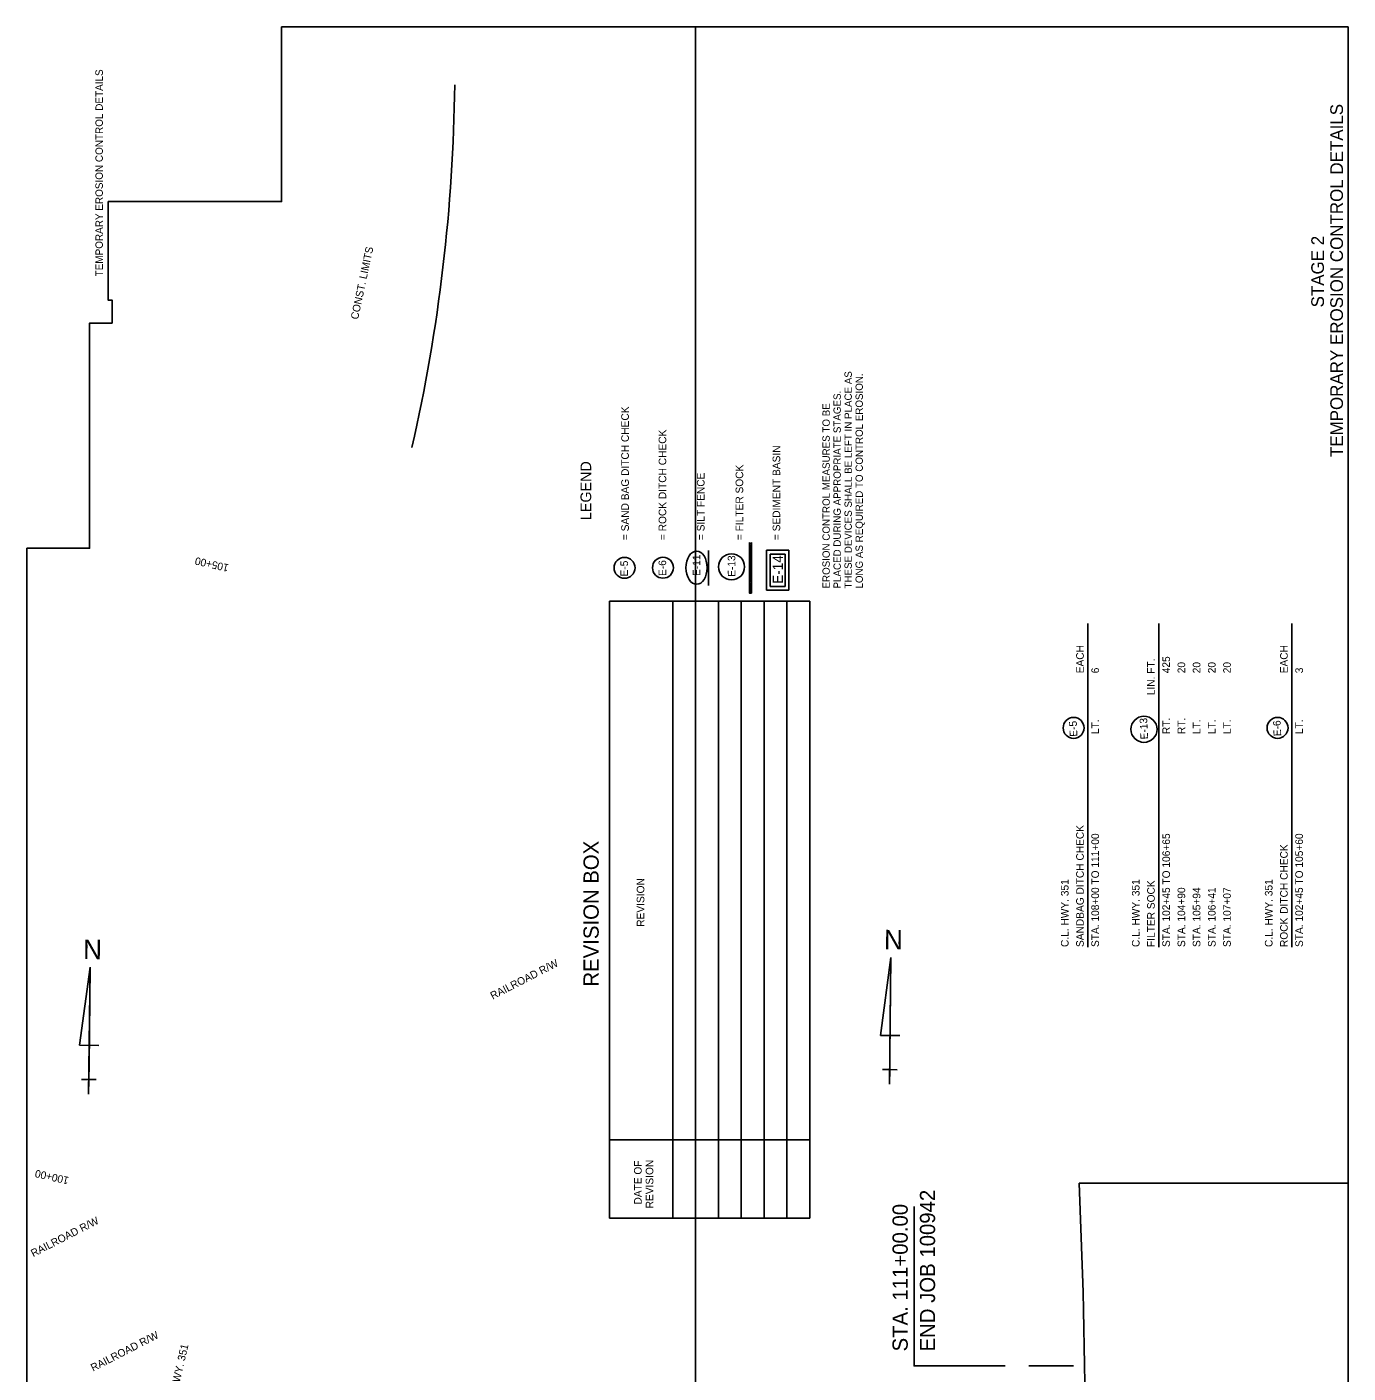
# Model space of a CAD drawing. Extents: x 1712161 to 1713203, y 549259 to 550855.
# Drawn here: x 1712161 to 1713203, y 549792 to 550855 of the extents above; entities that cross this region are included whole.
import ezdxf

# ---------------------------------------------------------------- set-up
doc = ezdxf.new("R2010")
doc.units = 0
for name, color, linetype in [('R_Contour Annot', 7, 'Continuous'), ('R_Contours', 7, 'Continuous'), ('R_Erosion', 7, 'Continuous'), ('R_Horz Alg', 7, 'Continuous'), ('R_Horz Alg Annot', 7, 'Continuous'), ('R_MOT', 7, 'Continuous'), ('R_Proposed Const Limits_Fill', 7, 'Continuous'), ('S_FENCE', 7, 'Continuous'), ('S_FIBER_OPTIC_CABLE', 7, 'Continuous')]:
    doc.layers.add(name, color=color, linetype=linetype)

msp = doc.modelspace()

# ---------------------------------------------------------------- linework, layer by layer
at = {"layer": 'R_Contour Annot'}
for points in [[(1712361.5, 550854.5), (1712688.2, 550854.5), (1712688.2, 549259.2), (1712160.6, 549259.2), (1712160.6, 550443.2), (1712210, 550443.2), (1712210, 550620.8), (1712227.8, 550620.8), (1712227.8, 550639), (1712224.6, 550639), (1712224.6, 550716.7)], [(1712361.5, 550854.5), (1712688.2, 550854.5), (1712688.2, 549259.2), (1712160.6, 549259.2), (1712160.6, 550443.2), (1712210, 550443.2), (1712210, 550620.8), (1712227.8, 550620.8), (1712227.8, 550639), (1712224.6, 550639), (1712224.6, 550716.7)], [(1712361.5, 550854.5), (1712688.2, 550854.5), (1712688.2, 549259.2), (1712160.6, 549259.2), (1712160.6, 550443.2), (1712210, 550443.2), (1712210, 550620.8), (1712227.8, 550620.8), (1712227.8, 550639), (1712224.6, 550639), (1712224.6, 550716.7)], [(1712361.5, 550854.5), (1712688.2, 550854.5), (1712688.2, 549259.2), (1712160.6, 549259.2), (1712160.6, 550443.2), (1712210, 550443.2), (1712210, 550620.8), (1712227.8, 550620.8), (1712227.8, 550639), (1712224.6, 550639), (1712224.6, 550716.7)], [(1712361.5, 550854.5), (1712688.2, 550854.5), (1712688.2, 549259.2), (1712160.6, 549259.2), (1712160.6, 550443.2), (1712210, 550443.2), (1712210, 550620.8), (1712227.8, 550620.8), (1712227.8, 550639), (1712224.6, 550639), (1712224.6, 550716.7)], [(1712361.5, 550854.5), (1712688.2, 550854.5), (1712688.2, 549259.2), (1712160.6, 549259.2), (1712160.6, 550443.2), (1712210, 550443.2), (1712210, 550620.8), (1712227.8, 550620.8), (1712227.8, 550639), (1712224.6, 550639), (1712224.6, 550716.7)], [(1712361.5, 550854.5), (1712688.2, 550854.5), (1712688.2, 549259.2), (1712160.6, 549259.2), (1712160.6, 550443.2), (1712210, 550443.2), (1712210, 550620.8), (1712227.8, 550620.8), (1712227.8, 550639), (1712224.6, 550639), (1712224.6, 550716.7)], [(1712361.5, 550854.5), (1712688.2, 550854.5), (1712688.2, 549259.2), (1712160.6, 549259.2), (1712160.6, 550443.2), (1712210, 550443.2), (1712210, 550620.8), (1712227.8, 550620.8), (1712227.8, 550639), (1712224.6, 550639), (1712224.6, 550716.7)], [(1712224.6, 550716.7), (1712361.5, 550716.7), (1712361.5, 550854.5)], [(1712224.6, 550716.7), (1712361.5, 550716.7), (1712361.5, 550854.5)], [(1712224.6, 550716.7), (1712361.5, 550716.7), (1712361.5, 550854.5)], [(1712224.6, 550716.7), (1712361.5, 550716.7), (1712361.5, 550854.5)], [(1712224.6, 550716.7), (1712361.5, 550716.7), (1712361.5, 550854.5)], [(1712224.6, 550716.7), (1712361.5, 550716.7), (1712361.5, 550854.5)], [(1712224.6, 550716.7), (1712361.5, 550716.7), (1712361.5, 550854.5)], [(1712224.6, 550716.7), (1712361.5, 550716.7), (1712361.5, 550854.5)]]:
    msp.add_lwpolyline(points, dxfattribs=at)
msp.add_lwpolyline([(1712688.2, 549259.2), (1712688.2, 550854.5), (1713202.9, 550854.5), (1713202.9, 549259.2)], close=True, dxfattribs=at)
msp.add_lwpolyline([(1712688.2, 549259.2), (1712688.2, 550854.5), (1713202.9, 550854.5), (1713202.9, 549259.2)], close=True, dxfattribs=at)
msp.add_lwpolyline([(1712688.2, 549259.2), (1712688.2, 550854.5), (1713202.9, 550854.5), (1713202.9, 549259.2)], close=True, dxfattribs=at)
msp.add_lwpolyline([(1712688.2, 549259.2), (1712688.2, 550854.5), (1713202.9, 550854.5), (1713202.9, 549259.2)], close=True, dxfattribs=at)
msp.add_lwpolyline([(1712688.2, 549259.2), (1712688.2, 550854.5), (1713202.9, 550854.5), (1713202.9, 549259.2)], close=True, dxfattribs=at)
msp.add_lwpolyline([(1712688.2, 549259.2), (1712688.2, 550854.5), (1713202.9, 550854.5), (1713202.9, 549259.2)], close=True, dxfattribs=at)
msp.add_lwpolyline([(1712688.2, 549259.2), (1712688.2, 550854.5), (1713202.9, 550854.5), (1713202.9, 549259.2)], close=True, dxfattribs=at)
msp.add_lwpolyline([(1712688.2, 549259.2), (1712688.2, 550854.5), (1713202.9, 550854.5), (1713202.9, 549259.2)], close=True, dxfattribs=at)
msp.add_lwpolyline([(1712688.2, 549259.2), (1712688.2, 550854.5), (1713202.9, 550854.5), (1713202.9, 549259.2)], close=True, dxfattribs=at)
at = {"layer": 'R_Contours'}
msp.add_arc((1711136.1, 550824.3), 1362.1, 347.2066, 359.3498, dxfattribs=at)
at = {"layer": 'R_Horz Alg'}
for p, q in [((1712842.3, 550120.2), (1712833.9, 550058.8)), ((1712841.2, 550020.2), (1712842.3, 550120.2)), ((1712842.3, 550120.2), (1712841.5, 550043.3)), ((1712210.4, 550112.5), (1712202.1, 550051)), ((1712209.3, 550012.5), (1712210.4, 550112.5)), ((1712210.4, 550112.5), (1712209.6, 550035.6)), ((1712202.1, 550051), (1712217.4, 550050.9)), ((1712833.9, 550058.8), (1712849.3, 550058.6)), ((1712841.2, 550020.2), (1712841.5, 550043.3)), ((1712209.3, 550012.5), (1712209.6, 550035.6)), ((1712841.3, 550031.8), (1712835.6, 550031.8)), ((1712835.6, 550031.8), (1712847.1, 550031.7)), ((1712841.2, 550020.2), (1712841.3, 550031.8)), ((1712209.4, 550024), (1712203.7, 550024.1)), ((1712203.7, 550024.1), (1712215.2, 550024)), ((1712209.3, 550012.5), (1712209.4, 550024))]:
    msp.add_line(p, q, dxfattribs=at)
at = {"layer": 'R_Horz Alg Annot'}
for p, q in [((1712688.2, 550854.5), (1712688.2, 550628)), ((1712620.2, 549914.6), (1712620.2, 550401.4)), ((1712620.2, 550401.4), (1712778.2, 550401.4)), ((1712670.2, 549914.6), (1712670.2, 550401.4)), ((1712688.2, 550408.7), (1712688.2, 550401.4)), ((1712688.2, 549914.6), (1712688.2, 550401.4)), ((1712706.2, 549914.6), (1712706.2, 550401.4)), ((1712724.2, 549914.6), (1712724.2, 550401.4)), ((1712742.2, 549914.6), (1712742.2, 550401.4)), ((1712760.2, 549914.6), (1712760.2, 550401.4)), ((1712778.2, 549914.6), (1712778.2, 550401.4)), ((1712997.6, 550128.3), (1712997.6, 550383.7)), ((1713053.6, 550128.3), (1713053.6, 550383.7)), ((1713158.5, 550128.3), (1713158.5, 550383.7)), ((1712620.2, 549976.4), (1712778.2, 549976.4)), ((1712620.2, 549914.6), (1712778.2, 549914.6)), ((1712688.2, 549914.6), (1712688.2, 549752.4))]:
    msp.add_line(p, q, dxfattribs=at)
for points in [[(1712932.4, 549798), (1712860.5, 549798), (1712860.5, 549923.8)], [(1712986.3, 549798), (1712951.1, 549798)]]:
    msp.add_lwpolyline(points, dxfattribs=at)
at = {"layer": 'R_MOT'}
msp.add_line((1712990.8, 549942.3), (1713202.9, 549942.3), dxfattribs=at)
msp.add_lwpolyline([(1713202.9, 549942.3), (1713202.9, 549259.2), (1712955.2, 549259.2)], dxfattribs=at)
msp.add_arc((1707466.7, 549704.5), 5529.2, 357.7082, 2.4649, dxfattribs=at)
at = {"layer": 'R_Proposed Const Limits_Fill'}
for p, q in [((1712730.7, 550407.6), (1712730.7, 550447.6)), ((1712732.2, 550446.1), (1712730.7, 550447.6)), ((1712732.2, 550444.6), (1712730.7, 550446.1)), ((1712732.2, 550443.2), (1712730.7, 550444.7)), ((1712732.2, 550441.8), (1712730.7, 550443.3)), ((1712732.2, 550447.5), (1712732.1, 550447.6)), ((1712732.2, 550447.6), (1712732.2, 550407.6)), ((1712732.2, 550440.4), (1712730.7, 550441.9)), ((1712732.2, 550439), (1712730.7, 550440.5)), ((1712732.2, 550437.6), (1712730.7, 550439.1)), ((1712732.2, 550436.2), (1712730.7, 550437.7)), ((1712732.2, 550434.7), (1712730.7, 550436.2)), ((1712732.2, 550433.3), (1712730.7, 550434.8)), ((1712732.2, 550431.9), (1712730.7, 550433.4)), ((1712732.2, 550430.5), (1712730.7, 550432)), ((1712744.1, 550441.6), (1712761.7, 550441.6)), ((1712744.1, 550410), (1712744.1, 550441.6)), ((1712747.1, 550412.9), (1712747.1, 550438.6)), ((1712747.1, 550438.6), (1712758.7, 550438.6)), ((1712758.7, 550412.9), (1712758.7, 550438.6)), ((1712761.7, 550410), (1712761.7, 550441.6)), ((1712732.2, 550429.1), (1712730.7, 550430.6)), ((1712732.2, 550427.7), (1712730.7, 550429.2)), ((1712732.2, 550426.3), (1712730.7, 550427.8)), ((1712732.2, 550424.8), (1712730.7, 550426.3)), ((1712732.2, 550423.4), (1712730.7, 550424.9)), ((1712732.2, 550422), (1712730.7, 550423.5)), ((1712732.2, 550420.6), (1712730.7, 550422.1)), ((1712732.2, 550419.2), (1712730.7, 550420.7)), ((1712732.2, 550417.8), (1712730.7, 550419.3)), ((1712732.2, 550416.4), (1712730.7, 550417.9)), ((1712732.2, 550414.9), (1712730.7, 550416.4)), ((1712732.2, 550413.5), (1712730.7, 550415)), ((1712732.2, 550412.1), (1712730.7, 550413.6)), ((1712732.2, 550410.7), (1712730.7, 550412.2)), ((1712732.2, 550409.3), (1712730.7, 550410.8)), ((1712747.1, 550412.9), (1712758.7, 550412.9)), ((1712732.2, 550407.9), (1712730.7, 550409.4)), ((1712731.1, 550407.6), (1712730.7, 550408)), ((1712732.2, 550407.6), (1712730.7, 550407.6)), ((1712744.1, 550410), (1712761.7, 550410))]:
    msp.add_line(p, q, dxfattribs=at)
msp.add_lwpolyline([(1712698.3, 550413.7), (1712698.2, 550441.5)], dxfattribs=at)
for centre, radius in [((1712632.1, 550427.7), 8.26), ((1712662.4, 550427.8), 8.26), ((1712716.5, 550428.5), 10.3), ((1712986.4, 550301.4), 8.26), ((1713147.3, 550301.4), 8.26)]:
    msp.add_circle(centre, radius, dxfattribs=at)
msp.add_ellipse((1712688.9, 550427.8), major_axis=(0, 13.1), ratio=0.638788, dxfattribs=at)
at = {"layer": 'S_FIBER_OPTIC_CABLE'}
msp.add_circle((1713041.9, 550300.3), 10.3, dxfattribs=at)

# ---------------------------------------------------------------- texts
at = {"layer": 'R_Erosion'}
for s, p in [('105+00', (1712320.3, 550430.3)), ('100+00', (1712194.1, 549946.9))]:
    msp.add_text(s, height=6, rotation=167.2066, dxfattribs=at).set_placement(p)
at = {"layer": 'R_Horz Alg'}
for p in [(1712836.7, 550126.7), (1712204.9, 550119)]:
    msp.add_text('N', height=15.4, rotation=359.3683, dxfattribs=at).set_placement(p)
at = {"layer": 'R_Horz Alg Annot'}
for s, height, rotation, p in [('TEMPORARY EROSION CONTROL DETAILS', 10, 90, (1713198.9, 550515.1)), ('STAGE 2', 10, 90, (1713183.9, 550633.2)), ('CONST. LIMITS', 6, 77.9685, (1712421.8, 550623.3)), ('EACH', 6, 90, (1712994.4, 550344.5)), ('425', 6, 90, (1713062.4, 550344.5)), ('EACH', 6, 90, (1713155.3, 550344.5)), ('6', 6, 90, (1713006.4, 550344.5)), ('   LIN. FT. ', 6, 90, (1713050.4, 550320.5)), ('20', 6, 90, (1713074.4, 550344.5)), ('20', 6, 90, (1713086.4, 550344.5)), ('20', 6, 90, (1713098.4, 550344.5)), ('20', 6, 90, (1713110.4, 550344.5)), ('3', 6, 90, (1713167.3, 550344.5)), ('LT.', 6, 90, (1713006.4, 550296.5)), ('RT.', 6, 90, (1713062.4, 550296.5)), ('RT.', 6, 90, (1713074.4, 550296.5)), ('LT.', 6, 90, (1713086.4, 550296.5)), ('LT.', 6, 90, (1713098.4, 550296.5)), ('LT.', 6, 90, (1713110.4, 550296.5)), ('LT.', 6, 90, (1713167.3, 550296.5)), ('SANDBAG DITCH CHECK', 6, 90, (1712994.4, 550128.5)), ('REVISION BOX', 12, 90, (1712611.7, 550097.3)), ('STA. 108+00 TO 111+00', 6, 90, (1713006.4, 550128.5)), ('STA. 102+45 TO 106+65', 6, 90, (1713062.4, 550128.5)), (' DITCH CHECK', 6, 90, (1713155.3, 550152.5)), ('STA. 102+45 TO 105+60', 6, 90, (1713167.3, 550128.5)), ('REVISION', 6, 90, (1712647.7, 550144.5)), ('C.L. HWY. 351', 6, 90, (1712982.4, 550128.5)), ('C.L. HWY. 351', 6, 90, (1713038.4, 550128.5)), ('FILTER SOCK', 6, 90, (1713050.4, 550128.5)), ('C.L. HWY. 351', 6, 90, (1713143.3, 550128.5)), ('STA. 104+90', 6, 90, (1713074.4, 550128.5)), ('STA. 105+94', 6, 90, (1713086.4, 550128.5)), ('STA. 106+41', 6, 90, (1713098.4, 550128.5)), ('STA. 107+07', 6, 90, (1713110.4, 550128.5)), ('ROCK', 6, 90, (1713155.3, 550128.5)), ('RAILROAD R/W', 6, 27.2066, (1712528.1, 550086.9)), ('DATE OF', 6, 90, (1712645.6, 549925.3)), ('REVISION', 6, 90, (1712654.8, 549922.3)), ('END JOB 100942', 12, 90, (1712877.1, 549809.4)), ('STA. 111+00.00', 12, 90, (1712855.5, 549809.4)), ('RAILROAD R/W', 6, 27.2066, (1712165.6, 549883.7)), ('RAILROAD R/W', 6, 27.2066, (1712212.8, 549793.4)), ('C.L. HWY. 351', 6, 76.7828, (1712275.9, 549762.4))]:
    msp.add_text(s, height=height, rotation=rotation, dxfattribs=at).set_placement(p)
at = {"layer": 'R_Proposed Const Limits_Fill'}
for s, height, rotation, p in [('THESE DEVICES SHALL BE LEFT IN PLACE AS ', 5.769, 90, (1712811.4, 550411.4)), ('LONG AS REQUIRED TO CONTROL EROSION.', 5.769, 90, (1712820.1, 550411.4)), ('PLACED DURING APPROPRIATE STAGES. ', 5.769, 90, (1712802.7, 550411.4)), ('= SAND BAG DITCH CHECK', 6, 90, (1712635.5, 550449.6)), ('EROSION CONTROL MEASURES TO BE', 5.769, 90, (1712794, 550411.4)), ('= ROCK DITCH CHECK', 6, 90, (1712665, 550449.6)), ('= SEDIMENT BASIN', 6, 90, (1712754.9, 550449.6)), ('LEGEND', 8.44, 90, (1712605.8, 550465.4)), ('= FILTER SOCK', 6, 90, (1712725.7, 550449.6)), ('= SILT FENCE', 6, 90, (1712695.2, 550449.6)), ('E-5 ', 6, 90, (1712634.8, 550420.9)), ('E-6 ', 6, 90.4005, (1712665, 550421.3)), ('E-11', 6, 90.2144, (1712691.9, 550421.3)), ('E-13', 6, 90.4005, (1712719.6, 550420.6)), ('E-14', 8, 89.9884, (1712757, 550415.1)), ('E-5 ', 6, 92.7601, (1712989.4, 550294.6)), ('E-6 ', 6, 92.7601, (1713150.2, 550295))]:
    msp.add_text(s, height=height, rotation=rotation, dxfattribs=at).set_placement(p)
at = {"layer": 'S_FENCE'}
msp.add_text('TEMPORARY EROSION CONTROL DETAILS', height=5.862, rotation=90, dxfattribs=at).set_placement((1712220.5, 550657.7))
at = {"layer": 'S_FIBER_OPTIC_CABLE'}
msp.add_text('E-13', height=6, rotation=92.7601, dxfattribs=at).set_placement((1713045.2, 550292.5))

doc.saveas('drawing.dxf')
